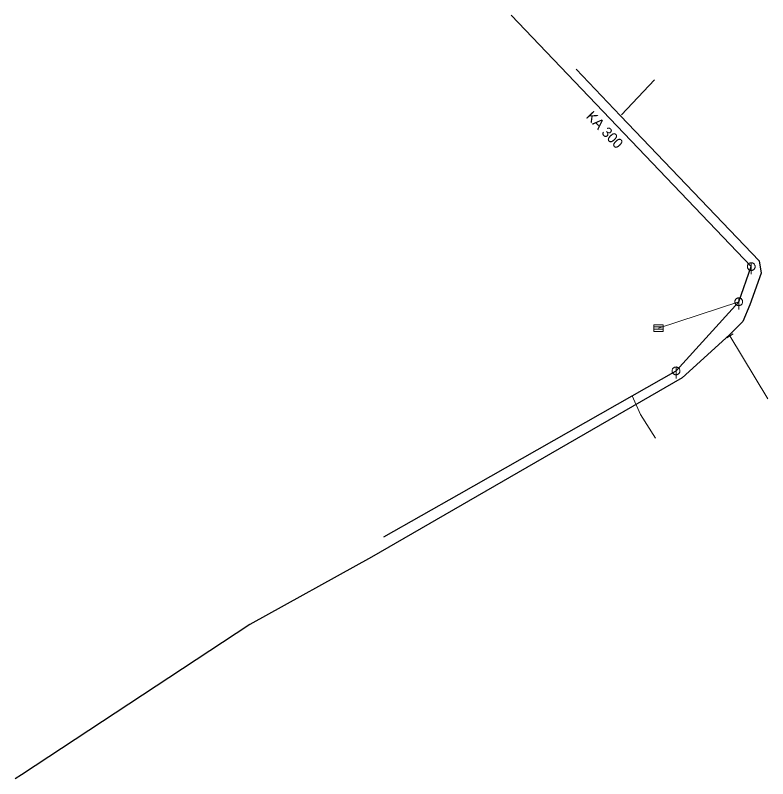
# Model space of a CAD drawing. Extents: x -687515 to -686506, y -974029 to -973461.
# Drawn here: x -687514.62 to -687465.82, y -973601.62 to -973552.14 of the extents above; entities that cross this region are included whole.
import ezdxf
from ezdxf.enums import TextEntityAlignment as Align

# ---------------------------------------------------------------- set-up
doc = ezdxf.new("R2010")
doc.units = 0
doc.header["$LTSCALE"] = 0.27
for name, color, linetype, lineweight in [('1', 7, 'Continuous', 13), ('11', 7, 'Continuous', 13), ('13', 7, 'Continuous', 13), ('14', 7, 'Continuous', 25), ('17', 7, 'Continuous', 25), ('22', 7, 'Continuous', 13), ('34', 7, 'Continuous', 13)]:
    doc.layers.add(name, color=color, linetype=linetype, lineweight=lineweight)

msp = doc.modelspace()

# ---------------------------------------------------------------- linework, layer by layer
at = {"layer": '11'}
msp.add_line((-687472.903, -973572.416), (-687467.7, -973570.71), dxfattribs=at)
msp.add_lwpolyline([(-687473.1, -973579.56), (-687474.07, -973578.01), (-687474.622, -973576.81)], dxfattribs=at)
at = {"layer": '13'}
for p, q in [((-687475.299, -973558.589), (-687473.16, -973556.32)), ((-687468.268, -973572.912), (-687465.82, -973577.01))]:
    msp.add_line(p, q, dxfattribs=at)
at = {"layer": '14', "lineweight": 13}
msp.add_line((-687468.302, -973572.855), (-687468.268, -973572.912), dxfattribs=at)
at = {"layer": '14'}
msp.add_lwpolyline([(-687490.71, -973585.949), (-687485.84, -973583.184), (-687474.622, -973576.809), (-687471.77, -973575.19), (-687467.699, -973570.71), (-687466.89, -973568.43), (-687482.469, -973552.14)], dxfattribs=at)
at = {"layer": '17'}
msp.add_lwpolyline([(-687478.239, -973555.64), (-687475.359, -973558.653), (-687466.37, -973568.059), (-687466.239, -973568.859), (-687466.98, -973570.91), (-687467.43, -973571.98), (-687468.302, -973572.855), (-687471.379, -973575.649), (-687491.515, -973587.261), (-687499.412, -973591.629), (-687514.23, -973601.37), (-687514.624, -973601.625)], dxfattribs=at)
at = {"layer": '22'}
for p, q in [((-687466.889, -973568.178), (-687466.89, -973568.922)), ((-687467.699, -973570.458), (-687467.7, -973571.201)), ((-687473.198, -973572.345), (-687472.6, -973572.345)), ((-687473.198, -973572.49), (-687472.6, -973572.49)), ((-687471.769, -973574.938), (-687471.77, -973575.681))]:
    msp.add_line(p, q, dxfattribs=at)
for points in [[(-687466.638, -973568.43), (-687466.639, -973568.404), (-687466.643, -973568.378), (-687466.649, -973568.352), (-687466.659, -973568.328), (-687466.671, -973568.304), (-687466.685, -973568.282), (-687466.702, -973568.261), (-687466.72, -973568.243), (-687466.741, -973568.226), (-687466.763, -973568.212), (-687466.787, -973568.2), (-687466.811, -973568.19), (-687466.837, -973568.184), (-687466.863, -973568.18), (-687466.889, -973568.178), (-687466.915, -973568.179), (-687466.941, -973568.183), (-687466.967, -973568.189), (-687466.992, -973568.199), (-687467.015, -973568.211), (-687467.037, -973568.225), (-687467.058, -973568.242), (-687467.076, -973568.26), (-687467.093, -973568.281), (-687467.107, -973568.303), (-687467.119, -973568.327), (-687467.129, -973568.351), (-687467.136, -973568.377), (-687467.14, -973568.403), (-687467.142, -973568.429), (-687467.141, -973568.455), (-687467.137, -973568.481), (-687467.13, -973568.507), (-687467.12, -973568.532), (-687467.108, -973568.555), (-687467.094, -973568.577), (-687467.077, -973568.598), (-687467.059, -973568.616), (-687467.038, -973568.633), (-687467.016, -973568.647), (-687466.993, -973568.659), (-687466.968, -973568.669), (-687466.942, -973568.676), (-687466.916, -973568.68), (-687466.89, -973568.682), (-687466.864, -973568.681), (-687466.838, -973568.677), (-687466.812, -973568.67), (-687466.788, -973568.66), (-687466.764, -973568.648), (-687466.742, -973568.634), (-687466.721, -973568.617), (-687466.703, -973568.599), (-687466.686, -973568.578), (-687466.672, -973568.556), (-687466.66, -973568.533), (-687466.65, -973568.508), (-687466.644, -973568.482), (-687466.64, -973568.456)], [(-687467.448, -973570.71), (-687467.449, -973570.684), (-687467.453, -973570.658), (-687467.459, -973570.632), (-687467.469, -973570.608), (-687467.481, -973570.584), (-687467.495, -973570.562), (-687467.512, -973570.541), (-687467.53, -973570.523), (-687467.551, -973570.506), (-687467.573, -973570.492), (-687467.597, -973570.48), (-687467.621, -973570.47), (-687467.647, -973570.464), (-687467.673, -973570.46), (-687467.699, -973570.458), (-687467.725, -973570.459), (-687467.751, -973570.463), (-687467.777, -973570.469), (-687467.802, -973570.479), (-687467.825, -973570.491), (-687467.847, -973570.505), (-687467.868, -973570.522), (-687467.886, -973570.54), (-687467.903, -973570.561), (-687467.917, -973570.583), (-687467.929, -973570.607), (-687467.939, -973570.631), (-687467.946, -973570.657), (-687467.95, -973570.683), (-687467.951, -973570.709), (-687467.951, -973570.735), (-687467.947, -973570.761), (-687467.94, -973570.787), (-687467.93, -973570.812), (-687467.918, -973570.835), (-687467.904, -973570.857), (-687467.887, -973570.878), (-687467.869, -973570.896), (-687467.848, -973570.913), (-687467.826, -973570.927), (-687467.803, -973570.939), (-687467.778, -973570.949), (-687467.752, -973570.956), (-687467.726, -973570.96), (-687467.7, -973570.962), (-687467.674, -973570.961), (-687467.648, -973570.957), (-687467.622, -973570.95), (-687467.598, -973570.94), (-687467.574, -973570.928), (-687467.552, -973570.914), (-687467.531, -973570.897), (-687467.513, -973570.879), (-687467.496, -973570.858), (-687467.482, -973570.836), (-687467.47, -973570.813), (-687467.46, -973570.788), (-687467.454, -973570.762), (-687467.45, -973570.736)], [(-687473.198, -973572.199), (-687472.6, -973572.199), (-687472.6, -973572.636), (-687473.198, -973572.636)], [(-687471.518, -973575.19), (-687471.519, -973575.164), (-687471.523, -973575.138), (-687471.529, -973575.112), (-687471.539, -973575.088), (-687471.551, -973575.064), (-687471.565, -973575.042), (-687471.582, -973575.021), (-687471.6, -973575.003), (-687471.621, -973574.986), (-687471.643, -973574.972), (-687471.667, -973574.96), (-687471.691, -973574.95), (-687471.717, -973574.944), (-687471.743, -973574.94), (-687471.769, -973574.938), (-687471.795, -973574.939), (-687471.821, -973574.943), (-687471.847, -973574.949), (-687471.872, -973574.959), (-687471.895, -973574.971), (-687471.917, -973574.985), (-687471.938, -973575.002), (-687471.956, -973575.02), (-687471.973, -973575.041), (-687471.987, -973575.063), (-687471.999, -973575.087), (-687472.009, -973575.111), (-687472.016, -973575.137), (-687472.02, -973575.163), (-687472.022, -973575.189), (-687472.021, -973575.215), (-687472.017, -973575.241), (-687472.01, -973575.267), (-687472, -973575.292), (-687471.988, -973575.315), (-687471.974, -973575.337), (-687471.957, -973575.358), (-687471.939, -973575.376), (-687471.918, -973575.393), (-687471.896, -973575.407), (-687471.873, -973575.419), (-687471.848, -973575.429), (-687471.822, -973575.436), (-687471.796, -973575.44), (-687471.77, -973575.441), (-687471.744, -973575.441), (-687471.718, -973575.437), (-687471.692, -973575.43), (-687471.668, -973575.42), (-687471.644, -973575.408), (-687471.622, -973575.394), (-687471.601, -973575.377), (-687471.583, -973575.359), (-687471.566, -973575.338), (-687471.552, -973575.316), (-687471.54, -973575.293), (-687471.53, -973575.268), (-687471.524, -973575.242), (-687471.52, -973575.216)]]:
    msp.add_lwpolyline(points, close=True, dxfattribs=at)
at = {"layer": '34'}
msp.add_line((-687468.48, -973573.04), (-687468.055, -973572.783), dxfattribs=at)

# ---------------------------------------------------------------- texts
at = {"layer": '1'}
msp.add_text('KA 300', height=0.6667, rotation=314, dxfattribs=at).set_placement((-687476.631, -973559.795), align=Align.CENTER)

doc.saveas('drawing.dxf')
